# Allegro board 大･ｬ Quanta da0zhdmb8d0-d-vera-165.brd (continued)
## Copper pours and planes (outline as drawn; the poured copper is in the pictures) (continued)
GT_SW_DRV1 on BOTTOM (solid shape): 176.95,47.53 176.95,47.23 177,47.18 177.51,47.18 177.61,47.28 177.61,47.63 177.72,47.73 179.2,47.73 179.51,47.42 179.51,44.76 178.53,43.77 176.52,43.77 175.37,44.92 175.37,47.61 175.5,47.73 176.75,47.73
GT_SW_DRV2 on TOP (solid shape): 185.57,44.66 185.57,43.91 185.48,43.82 184.27,43.82 183.99,44.1 183.99,44.61 184.13,44.74 185.48,44.74
GT_SW_DRV2 on BOTTOM (solid shape): 187.57,46.97 187.57,43.02 187.42,42.87 185.35,42.87 184.09,44.12 183.74,44.12 183.46,44.4 183.46,47.22 183.54,47.29 184.98,47.29 185.11,47.17 185.11,46.87 185.18,46.79 185.54,46.79 185.67,46.92 185.67,47.22 185.74,47.29 187.24,47.29
HDMI_5V on BOTTOM (solid shape): 20.74,52.79 21.38,52.79 21.55,52.62 21.55,52.61 21.61,52.54 21.69,52.48 21.69,52.48 21.95,52.22 21.95,51.07 21.91,51.04 20.69,51.04 20.07,51.66 17.07,51.66 16.65,51.24 15.82,51.24 15.74,51.32 15.74,52.26 16.16,52.67 16.17,52.68 16.32,52.77 16.41,52.92 16.42,52.93 16.46,52.98 16.64,52.98 16.66,53 20.54,53
HDMI_5V on IN1 (solid shape): 12.74,52.48 16.27,52.48 16.45,52.31 16.45,51.44 15.64,50.63 15.37,50.63 15.19,50.68 15,50.63 11.93,50.63 11.02,51.54 10.51,51.54 10.28,51.77 10.28,52.92 10.81,53.45 11.78,53.45
HP_RING2 on TOP (solid shape): 18.51,7.02 18.51,6.38 18,5.88 16.35,5.88 16.22,6 16.22,6.76 16.6,7.15 18.38,7.15
HP_RING2 on TOP (solid shape): 20.1,14.42 21.06,14.42 21.13,14.36 21.13,14.17 21.11,14.13 21.07,14.12 20.01,14.12 19.92,14.03 19.04,14.03 18.89,14.18 18.89,14.38 19.27,14.77 19.75,14.77
HP_RING2 on BOTTOM (solid shape): 17.62,7.78 17.62,6.13 17.37,5.88 16.35,5.88 16.22,6 16.22,7.78 16.35,7.91 17.49,7.91
HP_RING2 on IN1 (solid shape): outline of 136 points within 15.33,5.88 19.93,14.89
HP_SLEEVE on TOP (solid shape): 18.74,15.9 18.74,15.2 18.56,15.02 16.22,15.02 15.84,14.64 15.21,14.64 14.94,14.9 14.94,15.29 14.93,15.3 14.93,15.44 14.97,15.53 15.07,15.54 15.12,15.51 15.18,15.5 15.24,15.48 15.31,15.47 15.62,15.5 15.88,15.67 16.41,16.2 16.43,16.21 16.46,16.21 16.55,16.16 16.7,16.11 16.86,16.09 17.03,16.09 17.06,16.06 17.06,16.02 17.39,15.71 17.76,15.97 17.77,16.06 17.76,16.15 17.76,16.17 17.78,16.19 17.95,16.37 18.28,16.37
HP_SLEEVE on BOTTOM (solid shape): 16.76,15.22 16.76,14.01 16.76,12.76 16.58,12.58 15.49,12.58 15.33,12.73 15.33,14.69 15,15.02 15,15.55 15.21,15.76 16.22,15.76
HP_SLEEVE on IN1 (solid shape): outline of 107 points within 14.47,14.77 17.11,20.15
ISL_BOOST_LG on BOTTOM (solid shape): 55.08,13.87 55.08,13.52 54.83,13.28 53.82,13.28 53.74,13.37 53.74,14.03 53.81,14.1 54.85,14.1
ISL_BOOST_LG on BOTTOM (solid shape): 49.08,24.57 49.08,23.97 49.08,23.96 49.08,23.9 48.79,23.61 48.79,23.37 48.55,23.13 48.3,23.13 48.11,23.32 48.11,23.58 48.39,23.86 48.77,23.86 48.88,23.97 48.88,24.57 48.89,24.57 49.07,24.57
ISL_BOOST_UG on BOTTOM (solid shape): 53.81,17.65 53.81,17.33 53.59,17.11 53.59,16.35 53.53,16.3 53.12,16.3 53.09,16.32 53.09,17.58 53.34,17.83 53.63,17.83
ISL_BUCK_LG on BOTTOM (solid shape): 48.37,24.85 48.37,24.7 48.19,24.52 47.45,24.52 46.92,23.99 46.92,22.84 46.43,22.36 45.08,22.36 44.9,22.54 44.9,23.3 44.98,23.38 46.11,23.38 46.31,23.58 46.31,24.19 46.99,24.86 48.36,24.86
ISL_BUCK_PHASE on BOTTOM (solid shape): 45.66,26.02 46.27,26.02 46.98,25.31 47.74,25.31 47.78,25.27 48.35,25.27 48.38,25.25 48.38,25.09 48.36,25.07 47.77,25.07 47.71,25 46.91,25 46.66,24.75 46.17,24.75 46.09,24.82 46.09,25.2 45.99,25.31 45.99,25.36 45.93,25.36 45.92,25.38 45.79,25.38 45.64,25.53 45.64,25.57 45.6,25.57 45.59,25.59 44.98,25.59 44.87,25.69 44.87,26.27 44.92,26.32 45.36,26.32
ISL_BUCK_UG on BOTTOM (solid shape): 45.79,26.8 45.79,26.79 46.02,26.52 46.36,26.58 46.73,26.58 47.54,25.77 47.56,25.77 47.64,25.69 47.76,25.69 47.77,25.67 48.34,25.67 48.38,25.64 48.38,25.51 48.34,25.47 47.77,25.47 47.77,25.46 46.97,25.46 46.31,26.12 45.76,26.12 45.48,26.4 45.46,26.4 45.43,26.43 44.8,26.43 44.77,26.4 44.75,26.4 44.7,26.35 44.7,25.71 44.65,25.66 44.26,25.66 44.24,25.69 44.24,26.8 44.37,26.93 45.66,26.93
LCD_VCC on TOP (solid shape): 47.44,55.64 47.44,55.33 46.88,54.77 44.04,54.77 43.65,55.15 43.65,55.61 43.82,55.78 47.3,55.78
LCD_VCC on BOTTOM (solid shape): 46.7,55.91 46.7,55.16 46.54,55 45.18,55 44.14,53.96 42.44,53.96 42.13,54.26 42.13,55.15 42.21,55.23 43.4,55.23 44.21,56.04 46.58,56.04
LCD_VCC_OUT on TOP (solid shape): 46.73,58.76 46.73,56.32 46.58,56.17 45.69,56.17 45.56,56.29 45.56,56.3 45.64,56.52 45.57,56.74 45.56,56.76 45.56,56.89 45.59,57.36 45.12,57.44 45.11,57.44 45.05,57.44 44.92,57.31 44.92,56.29 44.8,56.17 44.16,56.17 44.06,56.27 44.06,58.12 43.78,58.4 43.78,58.76 43.86,58.83 46.65,58.83
MIC_N on TOP (solid shape): 21.18,13.37 21.18,13.11 20.41,12.35 19.78,12.35 19.65,12.48 19.65,12.99 20.08,13.42 21.13,13.42
MIC_P on TOP (solid shape): 18.64,14.51 18.64,14.08 18.81,13.9 21.1,13.9 21.13,13.88 21.13,13.65 21.1,13.62 20.03,13.62 19.78,13.37 18.13,13.37 17.62,13.88 17.62,14.77 17.75,14.89 18.25,14.89
SA_HG_DRV on TOP (solid shape): 164.31,29.71 164.37,29.65 164.37,29.13 163.96,28.72 161.69,28.72 161.44,28.48 160.77,28.48 160.5,28.75 160.5,29.18 160.68,29.35 163.69,29.35 163.74,29.4 163.74,29.69 163.77,29.71
SA_LG_DRV on TOP (solid shape): 162.46,31.33 162.46,31.03 162.41,30.99 161.89,30.99 161.63,31.25 160.78,31.25 160.59,31.44 160.59,31.63 160.59,31.65 160.6,31.67 160.8,31.86 160.81,31.87 161.92,31.87
SA_SW_DRV on TOP (solid shape): 157.02,32.37 157.02,32.13 157.6,31.55 157.6,31.27 157.44,31.11 157.15,31.11 156.67,31.59 156.21,31.59 156.02,31.78 156.02,32.41 156.06,32.45 156.94,32.45
SA_SW_DRV on BOTTOM (solid shape): 157.63,31.62 157.63,31.44 157.88,31.19 160.43,31.19 160.46,31.16 160.46,30.92 161.2,30.19 161.2,29.98 161.05,29.83 160.83,29.83 160.59,30.07 157.86,30.07 157.69,29.9 157.66,29.89 157.63,29.89 157.22,29.83 157.15,29.41 157.16,29.4 157.16,29.37 156.96,29.17 154.7,29.17 154.63,29.24 154.63,32.78 154.7,32.85 156.39,32.85
SPK_OUT_L_N on TOP (solid shape): 32.53,19.39 32.53,18.4 32.54,18.38 32.54,17.77 33.24,17.08 33.24,16.16 33.12,16.05 32.22,16.05 32.22,16.04 32.1,16.16 32.1,18.22 32.22,18.35 32.22,18.4 32.24,18.4 32.24,19.36 32.25,19.4 32.29,19.41 32.5,19.41
SPK_OUT_L_P on TOP (solid shape): 32.04,19.39 32.04,18.39 31.72,18.07 31.72,16.16 31.6,16.05 30.82,16.05 30.7,16.16 30.7,18.45 31.72,19.46 31.97,19.46
SPK_OUT_R_N on TOP (solid shape): 37.67,19.35 37.67,18.38 37.69,18.36 37.69,18.07 38.45,17.31 38.45,15.78 38.35,15.68 37.46,15.68 37.36,15.78 37.36,18.38 37.37,18.38 37.37,19.34 37.38,19.37 37.42,19.39 37.64,19.39
SPK_OUT_R_P on TOP (solid shape): 37.17,19.34 37.17,18.38 37.18,18.38 37.18,15.83 36.98,15.63 36.95,15.62 36.93,15.62 36.91,15.63 35.98,15.63 35.91,15.7 35.91,16.54 36.29,16.92 36.29,19.06 36.67,19.44 37.08,19.44
SW1 on BOTTOM (solid shape): 70.88,69.11 70.88,65.63 70.83,65.58 69,65.58 68.93,65.66 68.93,66.15 68.75,66.33 66.95,66.33 65.48,67.8 65.48,68.17 65.59,68.28 67.43,68.28 68.32,69.17 68.5,69.17 68.6,69.07 68.85,69.07 68.96,69.18 70.81,69.18
SW3 on BOTTOM (solid shape): 62.26,92.4 62.26,89.93 62.26,87.38 62.44,87.21 62.83,87.21 62.96,87.08 62.96,86.82 62.83,86.7 62.1,86.7 59.41,89.38 59.41,92.6 59.51,92.69 61.97,92.69
SW4 on BOTTOM (solid shape): 73.49,87.52 73.52,87.49 73.53,87.48 73.54,87.46 73.54,85.01 73.46,84.93 71.77,84.93 71.33,84.49 71.11,84.49 70.67,84.93 69.88,84.93 69.36,85.46 67.81,85.46 67.68,85.58 67.68,87.34 67.69,87.36 67.7,87.37 67.85,87.52 68.78,88.45 72.56,88.45
SWVR5 on BOTTOM (solid shape): 83.38,81.01 83.38,79.16 83.18,78.96 81.19,78.96 80.23,77.99 77.74,77.99 77.69,78.04 77.69,79.64 79.18,81.14 83.25,81.14
USB_C0_CC1_CONN on TOP (solid shape): 16.4,58.4 16.6,58.4 16.6,58.4 16.94,58.4 16.96,58.38 16.96,58.19 16.94,58.16 16.91,58.14 16.6,58.14 16.6,57.89 16.91,57.89 16.94,57.88 16.96,57.84 16.96,57.54 16.86,57.44 15.82,57.44 15.74,57.52 15.74,58.35 15.97,58.58 16.22,58.58
USB_C0_CC1_CONN on BOTTOM (solid shape): 9.42,65.49 9.43,65.48 9.59,65.26 9.85,65.22 9.88,65.22 9.9,65.21 9.92,65.18 9.92,64.85 9.71,64.64 9.23,64.64 9.11,64.75 8.91,64.75 8.55,65.11 8.45,65.11 8.4,65.16 8.4,65.44 8.48,65.51 9.39,65.51
USB_C0_CC1_CONN on BOTTOM (solid shape): 16.48,58.33 16.48,57.61 16.98,57.11 16.98,56.19 17.01,56.17 17.01,55.35 16.86,55.2 15.59,55.2 15.44,55.35 15.44,56.37 15.38,56.42 15.36,56.42 15.32,56.44 15.31,56.47 14.75,56.47 14.75,56.45 14.57,56.27 14.57,55.51 14.5,55.43 14.11,55.43 14.04,55.51 14.04,56.52 14.27,56.75 14.46,56.75 14.82,56.75 15,57.06 15,57.08 15.03,57.11 15.03,57.59 15.37,57.93 15.41,57.96 15.44,57.99 15.94,58.49 16.31,58.49
USB_C0_CC1_CONN on IN2 (solid shape): outline of 335 points within 8.53,57.34 16.88,65.77
USB_C0_CC2_CONN on TOP (solid shape): 14.95,57.18 15.07,57.18 15.1,57.15 15.49,57.15 15.58,57.07 15.58,56.81 15.71,56.68 15.71,56.65 16.38,55.98 16.41,55.98 16.48,55.91 16.93,55.91 16.96,55.89 16.96,55.66 16.59,55.66 16.59,55.41 16.93,55.41 16.96,55.38 16.96,55.15 16.83,55.02 15.36,55.02 15.23,55.15 15.23,56.17 15.11,56.29 14.52,56.29 14.44,56.22 14.44,55.28 14.32,55.15 13.89,55.15 13.75,55.29 13.75,56.32 13.76,56.34 14.14,56.76 14.45,57.24 14.45,57.24 14.52,57.31 14.83,57.31
USB_C0_CC2_CONN on IN1 (solid shape): 9.04,68.61 9.13,68.58 9.21,68.58 9.37,68.58 9.47,68.49 9.47,68.03 9.29,67.85 9.25,67.85 8.98,67.95 8.71,67.85 6.97,67.85 6.76,68.06 6.76,68.32 7.05,68.61 9.03,68.61
N16823303 on TOP (solid shape): 36.92,15.22 36.92,13.5 36.67,13.24 36.26,13.24 35.98,12.96 35.98,12.33 35.81,12.15 34.89,12.15 34.79,12.25 34.79,13.01 35.78,14 35.78,15.2 35.93,15.35 36.8,15.35
N16823303 on BOTTOM (solid shape): 36.48,13.09 37.97,13.09 38.04,13.01 38.04,12.2 37.94,12.1 35.1,12.1 34.82,12.38 34.82,12.86 35.04,13.09 36.47,13.09
N16823308 on TOP (solid shape): 38.57,15.25 38.57,13.5 38.32,13.24 37.2,13.24 37.08,13.37 37.08,14.21 37.43,14.56 37.43,15.32 37.48,15.37 38.45,15.37
N16823308 on BOTTOM (solid shape): 38.57,14.31 38.57,13.29 38.47,13.19 36.52,13.19 36.31,13.39 36.31,14.26 36.42,14.36 38.52,14.36
N16823317 on TOP (solid shape): 33.93,15.1 33.93,14.69 33.49,14.26 33.49,13.62 33.11,13.24 32.35,13.24 32.1,13.5 32.1,15.65 32.21,15.77 33.25,15.77
N16823317 on BOTTOM (solid shape): 37.99,15.45 37.99,14.61 37.94,14.56 36.29,14.56 34.73,13.01 34.63,12.98 34.56,13.07 34.26,13.39 33.88,13.17 33.87,13.16 33.84,13.14 32.4,13.14 32.25,13.29 32.25,14.37 32.32,14.43 35.09,14.43 36.13,15.48 37.97,15.48
N16823326 on TOP (solid shape): 30.7,15.77 31.6,15.77 31.72,15.65 31.72,13.88 31.59,13.75 31.08,13.75 30.95,13.62 30.35,13.62 30.07,13.9 30.07,15.27 30.57,15.78 30.7,15.78
N16823326 on BOTTOM (solid shape): 38.17,16.67 38.17,16.06 37.81,15.7 36.21,15.7 35.04,14.54 32.28,14.54 31.34,13.6 30.29,13.6 30.19,13.7 30.19,14.84 30.65,15.3 34.62,15.3 34.88,15.39 34.99,15.64 34.99,15.66 36.16,16.82 38.02,16.82
N17034135 on BOTTOM (solid shape): 166.34,30.55 166.34,28.19 166.02,27.87 158.05,27.87 157.87,28.06 157.85,28.1 157.85,29.11 159.83,29.11 159.83,28.55 159.85,28.53 159.85,28.5 159.87,28.5 159.93,28.45 161.09,28.45 161.33,28.7 161.33,29.06 161.22,29.18 161.2,29.21 161.17,29.25 161.12,29.29 161.07,29.32 161.02,29.35 160.96,29.36 160.91,29.37 160.85,29.37 160.79,29.36 160.73,29.35 160.68,29.32 160.64,29.3 160.59,29.3 160.48,29.19 159.91,29.19 159.88,29.16 159.85,29.16 159.85,29.13 159.83,29.11 157.85,29.11 157.85,29.79 157.93,29.88 160.42,29.88 160.64,29.88 160.79,29.73 161.09,29.73 161.3,29.94 161.3,29.94 161.62,30.27 164.86,30.27 165.32,30.73 165.57,30.97 165.91,30.97
N17035494 on TOP (solid shape): 83.32,61.69 83.74,61.69 83.85,61.57 83.85,59.1 84.39,58.56 84.4,58.52 84.4,58.07 84.22,57.89 82.64,57.89 82.36,58.17 81.3,58.17 81.25,58.22 81.25,58.79 82.27,58.79 82.27,58.98 81.48,58.98 81.48,58.79 81.25,58.79 81.25,59.09 81.35,59.19 81.48,59.19 81.48,59.19 82.26,59.19 82.26,59.19 82.36,59.19 82.67,59.49 82.67,60.87 82.49,61.04 81.91,61.04 81.81,61.15 81.81,61.71 82.85,61.71 82.85,61.9 82.06,61.9 82.06,61.71 81.81,61.71 81.81,61.91 81.98,62.09 82.92,62.09
N17037965 on TOP (solid shape): 217.24,30.74 217.24,28.81 217.14,28.71 215.38,28.71 215.36,28.74 215.36,30.69 215.54,30.87 217.11,30.87
N17037990 on BOTTOM (solid shape): 102.21,95.15 102.21,94.55 102.23,94.53 102.23,93.61 101.87,93.25 100.3,93.25 100.22,93.33 100.22,94.85 100.6,95.23 102.13,95.23
N17135957 on TOP (solid shape): 24.22,58.68 24.22,58.02 24.1,57.89 23.61,57.89 23.3,57.58 23.3,57.28 23.28,57.26 23.28,56.85 23.29,56.81 23.3,56.76 23.3,56.64 23.09,56.43 23.09,55.44 23.06,55.41 22.19,55.41 22.12,55.48 22.12,56.34 22.31,56.53 22.45,56.68 22.45,57.79 23.39,58.73 24.17,58.73
N17578279 on TOP (solid shape): 158.3,31.04 158.3,30.7 157.95,30.34 155.53,30.34 155.29,30.59 155.29,30.94 155.45,31.11 156.9,31.11 157.04,30.98 157.6,30.98 157.75,31.13 158.21,31.13
N17586894 on TOP (solid shape): 184.9,40.38 184.9,39.87 184.68,39.65 183.71,39.65 183.47,39.88 183.47,40.4 183.59,40.52 184.77,40.52
N17586894 on BOTTOM (solid shape): 185.82,40.76 185.84,40.74 185.84,39.59 185.83,39.58 185.41,39.58 185.4,39.58 185.15,39.58 184.16,38.59 182.89,38.59 181.66,37.36 180.35,37.36 180.26,37.45 180.26,39.68 180.57,40 183.53,40 184.29,40.76 185.63,40.76
N17618076 on TOP (solid shape): 175.67,41.83 175.67,41.2 175.22,40.75 174.77,40.75 174.7,40.82 174.7,41.73 174.92,41.94 175.56,41.94
N17618076 on BOTTOM (solid shape): 175.53,41.76 176.97,41.76 177.02,41.7 177.02,40.56 176.94,40.47 176.32,40.47 174.99,39.13 174.99,37.88 174.9,37.79 174.06,37.79 173.75,38.09 173.75,40.75 173.51,41 171.56,41 171.35,41.22 171.35,41.22 171.35,42.3 171.5,42.45 174.84,42.45
N17621976 on TOP (solid shape): 179.61,45 179.61,44.6 179.54,44.53 178.71,44.53 178.52,44.34 177.9,44.34 177.82,44.43 177.82,45.2 177.9,45.28 179.33,45.28
N17622303 on TOP (solid shape): 186.94,45.39 186.94,43.69 185.93,42.68 185.46,42.68 185.37,42.77 185.37,43.21 185.88,43.72 185.88,44.47 186.05,44.64 186.05,45.32 186.25,45.52 186.81,45.52
N17648742 on TOP (solid shape): 171.05,37.11 171.05,35.01 170.93,34.89 170.43,34.89 170.23,35.08 170.23,36.25 170.37,36.39 170.37,37.17 170.51,37.3 170.87,37.3
N17648742 on BOTTOM (solid shape): 170.12,36.91 170.12,36.31 171.06,35.37 171.06,35.19 171.96,34.29 171.96,33.41 171.43,32.88 171.43,32.87 171.2,32.64 171.2,31.47 171.14,31.4 169.97,31.4 169.73,31.64 169.73,33.47 169.38,33.82 169.38,34.78 169.38,34.9 168.89,35.39 168.89,36.92 168.94,36.97 170.06,36.97
N17675286 on TOP (solid shape): 166.86,37.25 166.86,36.88 166.77,36.78 166.12,36.78 165.86,36.51 164.25,36.51 164.08,36.69 164.08,37.14 164.37,37.43 166.68,37.43
N17700362 on BOTTOM (solid shape): 44.37,31.89 44.37,27.16 44.05,26.84 44.05,25.93 43.78,25.66 40.71,25.66 40.23,25.18 40.23,24.93 39.9,24.59 38.78,24.59 38.5,24.87 38.5,25.89 38.51,25.92 38.53,25.93 38.7,26.1 38.71,26.35 38.71,26.37 38.73,26.4 38.75,26.42 40.02,26.42 40.48,26.88 40.48,30.37 41.02,30.91 41.02,31.99 41.04,32.01 44.24,32.01
N17700446 on BOTTOM (solid shape): 51.31,14.08 53.51,14.08 53.59,14 53.59,12.94 53.38,12.73 45.76,12.73 45.69,12.81 45.69,14.77 45.86,14.94 50.45,14.94
N17700456 on BOTTOM (solid shape): 44.73,23.32 44.73,21.69 44.87,21.55 49.39,21.55 49.47,21.48 49.47,19.67 49.06,19.27 44.39,19.27 44.16,19.49 44.16,20.78 43.76,21.19 43.02,21.19 42.84,21.37 42.84,23.27 42.97,23.4 44.65,23.4
N17714367 on BOTTOM (solid shape): 42.11,22.79 42.11,22.61 42.59,22.13 42.59,21.39 42.46,21.27 41.72,21.27 41.62,21.37 41.62,21.72 41.19,22.16 40.78,22.16 40.61,22.33 40.61,22.72 40.96,23.07 41.83,23.07
N17724245 on BOTTOM (solid shape): 59.11,28.61 59.11,24.14 58.85,23.88 55.62,23.88 55.52,23.98 55.52,28.07 55.62,28.18 56.73,28.18 57.16,28.6 57.17,28.61 57.29,28.69 57.37,28.81 57.38,28.82 57.5,28.94 58.78,28.94
N18167653 on TOP (solid shape): 174.31,22.84 174.35,22.83 174.36,22.79 174.36,22.32 174.58,22.32 174.58,22.79 174.6,22.83 174.63,22.84 174.85,22.84 174.86,22.83 174.86,22.32 174.87,22.32 174.87,20.61 174.62,20.35 173.78,20.35 173.7,20.28 173.7,19.31 173.6,19.21 172.89,19.21 172.79,19.31 172.79,22.39 173.25,22.84
N18366094 on TOP (solid shape): 30,71.28 30.02,71.28 30.04,71.26 30.3,71.13 30.57,71.23 30.64,71.26 30.71,71.23 30.98,71.13 31.23,71.26 31.25,71.28 31.27,71.28 32.22,71.28 32.48,71.03 32.48,69.76 32.35,69.63 31.21,69.63 30.83,70.01 27.07,70.01 27.03,70.02 27.02,70.06 27.02,70.77 27.53,71.28
N18401065 on BOTTOM (solid shape): 99.03,87.49 99.03,87.13 99.18,86.98 99.2,86.98 99.23,86.96 99.28,86.94 99.33,86.93 99.38,86.93 99.43,86.93 99.48,86.94 99.53,86.96 99.57,86.98 99.76,86.98 99.79,86.95 100.63,86.95 100.83,86.75 100.83,85.94 100.09,85.2 99.43,85.2 98.52,86.11 98.52,86.55 100.58,86.55 100.58,86.75 99.79,86.75 99.79,86.55 98.52,86.55 98.52,87.54 98.57,87.59 98.93,87.59

Small or netless copper shapes (teardrops, artwork), in the pictures only: 71 on TOP, 19 on BOTTOM, 11 on IN1, 28 on IN2

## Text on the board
Ref Des/Silkscreen Bottom: MODEL:ZHD | DA0ZHDMB8D0 REV:D
User.Comments: PARTITION_2 | PARTITION_3 | 30.0x32.0 | CARD BOARD CONN | BELLINZONA MB PCBA DXF -V23 20170223 | OUT-LINE
Ref Des/Silkscreen Top: DA0ZHDMB8D0 REV:D
BODY_CENTER: TOP-HIGHT
DIMENSION: BOT-HIGHT
User.6: TOP-COMPNOENT | USB3.0 | AUDIO JACK | HDMI | TYPEC | CPU BKT | HALL SENSOR
User.7: BOT-COMPNOENT | SPK CONN | BAT CONN | CPU | FAN CONN | LED | LVDS CONN(FPC TYPE) | 11.6" KB CONN. | TP CONN | WLAN | M2 NUT
User.8: TOP-COMPNOENT | USB3.0 | AUDIO JACK | HDMI | TYPEC | CPU BKT | HALL SENSOR
User.9: BOT-COMPNOENT | SPK CONN | BAT CONN | CPU | FAN CONN | CARD BOARD CONN | LED | LVDS CONN(FPC TYPE) | 11.6" KB CONN. | TP CONN | WLAN | M2 NUT
User.12: +VCCPRIM_CORE | +VUSBC1_VBUS_CONN | GND | +V_BOOSTIN | +V5A | +V1P00A | +V1P00S_VCCSTG | +VCCSA | +VCCCORE | +VBATA | +VCCGT
User.25: TOP-HIGHT
User.26: BOT-HIGHT
User.28: GND
User.29: GND
User.30: GND
User.33: REV:A-7
User.45: PadStack_Check:Dec 29 12:31:30 2016 | TP check:Dec 29 13:59:24 2016 | XY-Check acute:Dec 29 12:44:56 2016 | XY-Create plane:Dec 29 12:41:39 2016 | XY-Cross plane-BOTTOM-SGND2:Dec 29 12:46:48 2016 | XY-Cross plane-IN1-SGND1:Dec 29 12:46:31 2016 | XY-Cross plane-IN1-SGND:Dec 29 12:46:36 2016 | XY-Cross plane-IN2-SGND2:Dec 29 12:46:39 2016 | XY-Cross plane-IN2-SVCC:Dec 29 12:46:43 2016 | XY-Cross plane-TOP-SGND:Dec 29 12:46:21 2016 | XY-Dxf to pin check:Dec 29 12:34:48 2016 | XY-Etch ref-BOTTOM-SGND2:Dec 29 12:46:54 2016 | XY-Etch ref-IN1-SGND1:Dec 29 12:46:36 2016 | XY-Etch ref-IN1-SGND:Dec 29 12:46:39 2016 | XY-Etch ref-IN2-SGND2:Dec 29 12:46:43 2016 | XY-Etch ref-IN2-SVCC:Dec 29 12:46:48 2016 | XY-Etch ref-TOP-SGND:Dec 29 12:46:30 2016 | XY-Mask check:Dec 29 13:36:30 2016 | XY-Outline check:Dec 29 13:34:26 2016 | XY-PadStack_Check:Dec 29 12:31:30 2016 | XY-Plane net check:Dec 29 12:39:48 2016 | XY-Prop check:Dec 29 12:46:10 2016 | XY-TP check:Dec 29 13:59:24 2016 | XY-shape min check:Dec 29 12:30:55 2016 | XY-via check:Dec 29 12:48:15 2016 | check acute:Dec 29 12:44:55 2016 | create plane:Dec 29 12:41:39 2016 | cross plane-BOTTOM-SGND2:Dec 29 12:46:48 2016 | cross plane-IN1-SGND1:Dec 29 12:46:31 2016 | cross plane-IN1-SGND:Dec 29 12:46:36 2016 | cross plane-IN2-SGND2:Dec 29 12:46:39 2016 | cross plane-IN2-SVCC:Dec 29 12:46:43 2016 | cross plane-TOP-SGND:Dec 29 12:46:21 2016 | dxf to pin check:Dec 29 12:34:48 2016 | etch ref-BOTTOM-SGND2:Dec 29 12:46:54 2016 | etch ref-IN1-SGND1:Dec 29 12:46:36 2016 | etch ref-IN1-SGND:Dec 29 12:46:39 2016 | etch ref-IN2-SGND2:Dec 29 12:46:43 2016 | etch ref-IN2-SVCC:Dec 29 12:46:48 2016 | etch ref-TOP-SGND:Dec 29 12:46:30 2016 | outline check:Dec 29 13:34:26 2016 | plane net check:Dec 29 12:39:48 2016 | prop check:Dec 29 12:46:10 2016 | shape min check:Dec 29 12:30:55 2016 | via check:Dec 29 12:48:15 2016 | PT_TOP | PT_BOT | FIGURE | TYPE | Oblong | Circle | SIZE | 55.0x24.0 | 57.0x24.0 | 63.0x24.0 | 71.0x31.0 | 100.0x31.0 | 102.0x31.0 | 236.0x157.0 | 9.8 | 10.0 | 12.0 | 14.0 | 18.0 | 22.0 | 24.0 | 32.0 | 98.0 | 142.0 | 146.0 | 158.0 | 217.0 | 47.0 | 67.0 | 197.0 | DRILL CHART: TOP to BOTTOM | ALL UNITS ARE IN MILS | PLATED | NON-PLATED | ROTATION | 0.000 | 90.000 | - | QTY | 7 | 2 | 4 | 1 | 21 | 77 | 3813 | 8 | 731 | 32 | 12 | 19 | 9 | 3 | 4725 | TOTAL HOLES:
